// Mitsubishi GX Works2 project: 实例训练（光电信号检测）   PLC: FX3U/FX3UC

PROGRAM MAIN
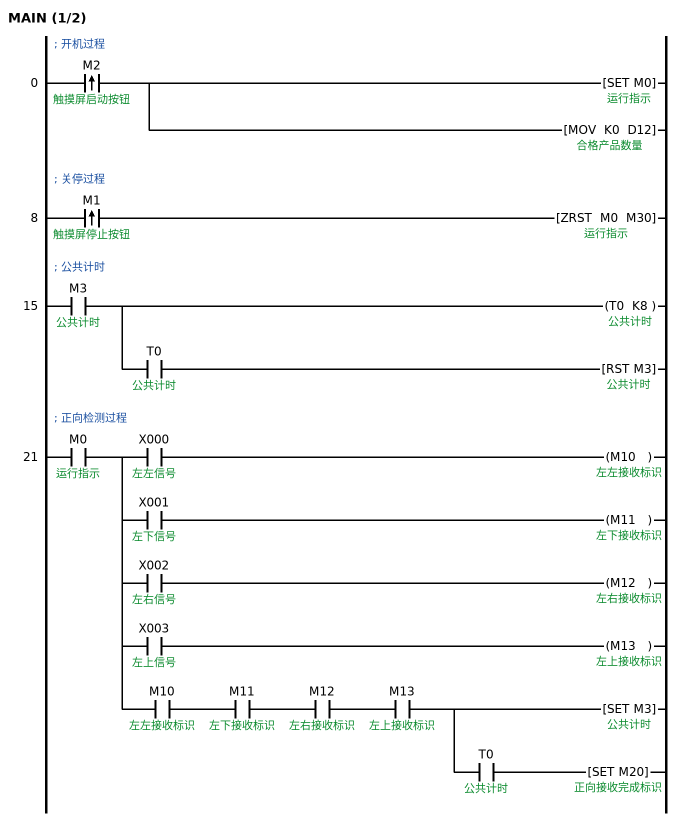
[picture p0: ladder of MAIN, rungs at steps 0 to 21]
; 开机过程
0     LDP     M2  ; 触摸屏启动按钮
      SET     M0  ; 运行指示
      MOV     K0 D12  ; 合格产品数量
        [note] 产品计数清零
; 关停过程
8     LDP     M1  ; 触摸屏停止按钮
      ZRST    M0 M30
; 公共计时
15    LD      M3  ; 公共计时
      OUT     T0 K8  ; 公共计时
      AND     T0  ; 公共计时
      RST     M3  ; 公共计时
; 正向检测过程
21    LD      M0  ; 运行指示
      MPS
      AND     X000  ; 左左信号
      OUT     M10  ; 左左接收标识
      MRD
      AND     X001  ; 左下信号
      OUT     M11  ; 左下接收标识
      MRD
      AND     X002  ; 左右信号
      OUT     M12  ; 左右接收标识
      MRD
      AND     X003  ; 左上信号
      OUT     M13  ; 左上接收标识
      MPP
      AND     M10  ; 左左接收标识
      AND     M11  ; 左下接收标识
      AND     M12  ; 左右接收标识
      AND     M13  ; 左上接收标识
      SET     M3  ; 公共计时
      AND     T0  ; 公共计时
      SET     M20  ; 正向接收完成标识
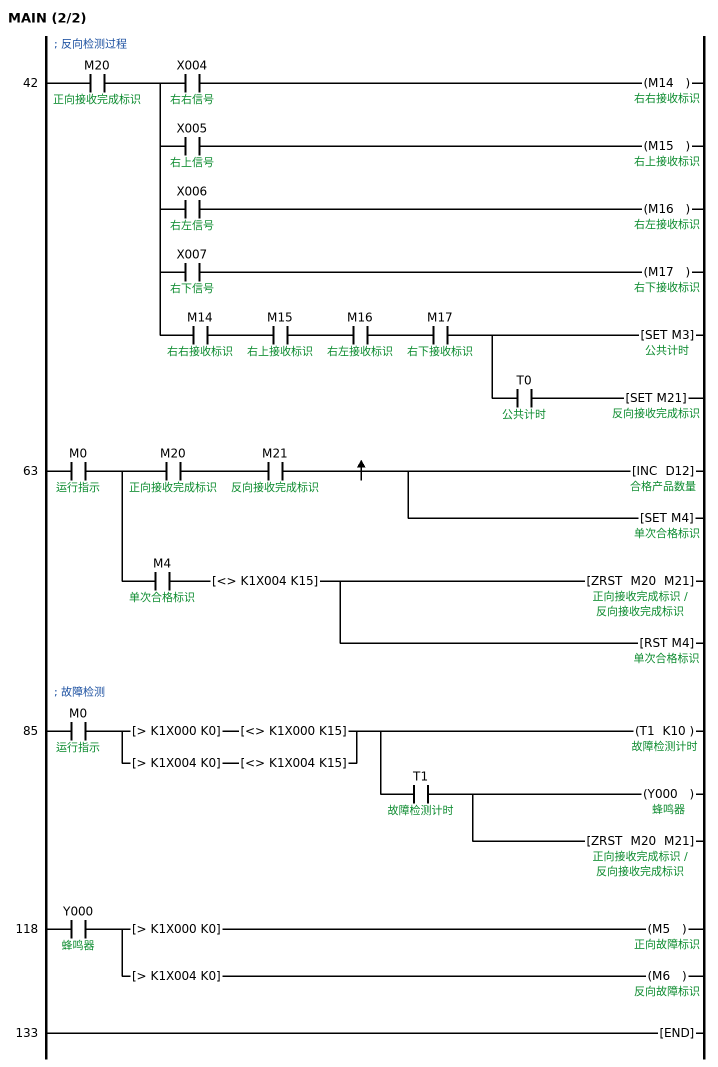
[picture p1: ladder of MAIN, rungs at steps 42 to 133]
; 反向检测过程
42    LD      M20  ; 正向接收完成标识
      MPS
      AND     X004  ; 右右信号
      OUT     M14  ; 右右接收标识
      MRD
      AND     X005  ; 右上信号
      OUT     M15  ; 右上接收标识
      MRD
      AND     X006  ; 右左信号
      OUT     M16  ; 右左接收标识
      MRD
      AND     X007  ; 右下信号
      OUT     M17  ; 右下接收标识
      MPP
      AND     M14  ; 右右接收标识
      AND     M15  ; 右上接收标识
      AND     M16  ; 右左接收标识
      AND     M17  ; 右下接收标识
      SET     M3  ; 公共计时
      AND     T0  ; 公共计时
      SET     M21  ; 反向接收完成标识
63    LD      M0  ; 运行指示
      MPS
      AND     M20  ; 正向接收完成标识
      AND     M21  ; 反向接收完成标识
      MEP
      INC     D12
      SET     M4  ; 单次合格标识
      MPP
      AND     M4  ; 单次合格标识
      AND<>   K1X004 K15  ; 右右信号
      ZRST    M20 M21
      RST     M4  ; 单次合格标识
; 故障检测
85    LD      M0  ; 运行指示
      LD>     K1X000 K0  ; 左左信号
      AND<>   K1X000 K15  ; 左左信号
      LD>     K1X004 K0  ; 右右信号
      AND<>   K1X004 K15  ; 右右信号
      ORB
      ANB
      OUT     T1 K10  ; 故障检测计时
      AND     T1  ; 故障检测计时
      OUT     Y000  ; 蜂鸣器
      ZRST    M20 M21
118   LD      Y000  ; 蜂鸣器
      MPS
      AND>    K1X000 K0  ; 左左信号
      OUT     M5  ; 正向故障标识
      MPP
      AND>    K1X004 K0  ; 右右信号
      OUT     M6  ; 反向故障标识
133   END
END_PROGRAM

// device comments not shown above
M22  ; 反向接收故障标识
M23  ; 反向移开故障标识
C0  ; 合格产品计数
D0  ; 正向检测反馈
D1  ; 反向检测反馈
D2  ; 反向检测通过标识
D3  ; 反向移开标识
D10  ; 正向完成数量
D11  ; 反向完成数量
D200  ; 上次合格产品计数
